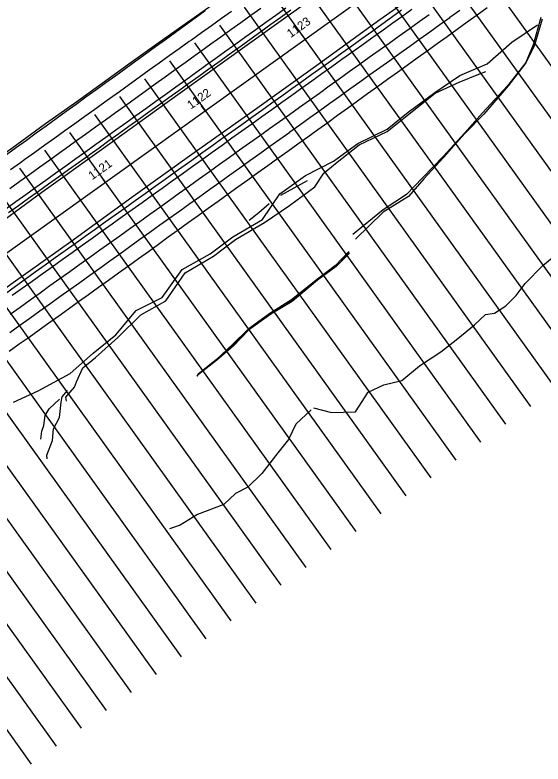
# Model space of a CAD drawing. Extents: x -354 to 8821, y -19535 to 19639.
# Drawn here: x 7812 to 8242, y 1583 to 2193 of the extents above; entities that cross this region are included whole.
import ezdxf

# ---------------------------------------------------------------- set-up
doc = ezdxf.new("R2010")
doc.units = 0
for name, color, linetype in [('PV_X_COP', 7, 'Continuous'), ('PV_X_EOP', 7, 'Continuous'), ('PV_X_Shoulder_Aggregate', 7, 'Continuous'), ('RW_X_CL_50', 7, 'Continuous'), ('SC_Scratch1', 7, 'Continuous'), ('SV_X_Edge_of_Slip', 7, 'Continuous'), ('SV_X_Toe_of_Slope', 7, 'Continuous'), ('SV_X_Top_of_Bank', 7, 'Continuous')]:
    doc.layers.add(name, color=color, linetype=linetype)

msp = doc.modelspace()

# ---------------------------------------------------------------- linework, layer by layer
at = {"layer": 'PV_X_COP'}
for points in [[(7807.73, 2051.83), (7815.85, 2057.67), (7823.97, 2063.5), (7832.09, 2069.34), (7840.21, 2075.17), (7848.33, 2081.01), (7853.03, 2084.39), (7861.15, 2090.22), (7869.27, 2096.06), (7877.39, 2101.9), (7885.51, 2107.73), (7893.63, 2113.57), (7901.75, 2119.41), (7909.87, 2125.24), (7917.99, 2131.08), (7926.11, 2136.92), (7934.23, 2142.75), (7942.35, 2148.59), (7950.47, 2154.43), (7958.59, 2160.27), (7963.29, 2163.64), (7963.29, 2163.64), (7971.41, 2169.48), (7979.53, 2175.32), (7987.65, 2181.15), (7995.77, 2186.99), (8003.89, 2192.82), (8012.01, 2198.66)], [(7807.89, 1949.36), (7816.02, 1955.18), (7824.15, 1961.01), (7832.27, 1966.83), (7840.4, 1972.66), (7848.53, 1978.48), (7856.66, 1984.3), (7864.79, 1990.13), (7872.92, 1995.95), (7881.05, 2001.77), (7889.18, 2007.59), (7897.14, 2013.29), (7905.27, 2019.11), (7913.4, 2024.93), (7921.53, 2030.76), (7929.66, 2036.58), (7937.79, 2042.4), (7945.92, 2048.22), (7954.05, 2054.04), (7962.18, 2059.86), (7970.32, 2065.68), (7978.45, 2071.5), (7986.58, 2077.32), (7994.71, 2083.14), (8002.85, 2088.95), (8010.98, 2094.77), (8019.11, 2100.59), (8027.07, 2106.28), (8035.2, 2112.1), (8043.34, 2117.92), (8051.47, 2123.73), (8059.61, 2129.55), (8067.74, 2135.37), (8075.88, 2141.18), (8084.01, 2147), (8092.15, 2152.81), (8100.28, 2158.63), (8108.42, 2164.44), (8116.55, 2170.26), (8124.69, 2176.07), (8132.82, 2181.89), (8140.96, 2187.7), (8149.1, 2193.51)]]:
    msp.add_lwpolyline(points, dxfattribs=at)
at = {"layer": 'PV_X_EOP'}
for points in [[(7804.49, 2035.27), (7812.61, 2041.1), (7820.74, 2046.93), (7828.86, 2052.76), (7836.98, 2058.6), (7845.11, 2064.43), (7853.23, 2070.26), (7861.35, 2076.09), (7869.47, 2081.93), (7877.6, 2087.76), (7885.72, 2093.59), (7885.88, 2093.71), (7894, 2099.54), (7902.12, 2105.38), (7910.24, 2111.21), (7918.36, 2117.05), (7926.48, 2122.89), (7934.6, 2128.72), (7942.72, 2134.56), (7950.84, 2140.39), (7958.96, 2146.23), (7967.08, 2152.07), (7967.24, 2152.18), (7967.24, 2152.18), (7975.36, 2158.02), (7983.48, 2163.86), (7991.6, 2169.7), (7999.72, 2175.53), (8007.84, 2181.37), (8015.97, 2187.2), (8024.09, 2193.04), (8032.21, 2198.87)], [(7807.76, 1934.57), (7815.89, 1940.4), (7824.02, 1946.22), (7832.14, 1952.05), (7840.27, 1957.88), (7848.4, 1963.7), (7856.53, 1969.53), (7864.65, 1975.35), (7872.78, 1981.18), (7880.91, 1987), (7889.04, 1992.83), (7897.16, 1998.66), (7905.29, 2004.48), (7905.45, 2004.6), (7913.58, 2010.42), (7921.71, 2016.25), (7929.84, 2022.07), (7937.96, 2027.9), (7946.09, 2033.72), (7954.22, 2039.55), (7962.35, 2045.37), (7970.48, 2051.2), (7978.61, 2057.02), (7986.73, 2062.84), (7994.86, 2068.67), (8002.99, 2074.49), (8011.12, 2080.32), (8019.25, 2086.14), (8027.38, 2091.97), (8035.51, 2097.79), (8035.67, 2097.9), (8043.79, 2103.73), (8051.92, 2109.55), (8060.05, 2115.38), (8068.18, 2121.2), (8076.31, 2127.02), (8084.44, 2132.85), (8092.57, 2138.67), (8100.7, 2144.5), (8108.83, 2150.32), (8116.96, 2156.14), (8125.09, 2161.97), (8133.22, 2167.79), (8141.35, 2173.61), (8149.48, 2179.44), (8157.61, 2185.26), (8165.74, 2191.08), (8165.89, 2191.2), (8174.02, 2197.02)], [(8134.86, 2197.46), (8126.73, 2191.64), (8118.6, 2185.82), (8110.47, 2180), (8102.34, 2174.18), (8094.21, 2168.35), (8086.08, 2162.53), (8077.95, 2156.71), (8069.82, 2150.89), (8061.69, 2145.06), (8053.56, 2139.24), (8045.43, 2133.42), (8037.3, 2127.6), (8029.17, 2121.77), (8021.03, 2115.94), (8012.9, 2110.12), (8004.78, 2104.3), (7996.65, 2098.47), (7988.52, 2092.65), (7980.39, 2086.82), (7972.26, 2081), (7964.13, 2075.18), (7956, 2069.35), (7947.87, 2063.53), (7939.74, 2057.7), (7931.61, 2051.88), (7923.48, 2046.06), (7915.36, 2040.23), (7907.23, 2034.41), (7899.1, 2028.58), (7890.96, 2022.75), (7882.83, 2016.93), (7874.7, 2011.1), (7866.58, 2005.28), (7858.45, 1999.45), (7850.32, 1993.62), (7842.19, 1987.8), (7834.06, 1981.97), (7825.94, 1976.15), (7817.81, 1970.32), (7809.68, 1964.5)], [(7988, 2196.04), (7979.88, 2190.2), (7971.76, 2184.37), (7963.64, 2178.53), (7955.52, 2172.69), (7953.69, 2171.38), (7953.69, 2171.38), (7945.57, 2165.54), (7937.45, 2159.7), (7929.33, 2153.87), (7921.21, 2148.03), (7913.09, 2142.19), (7904.97, 2136.36), (7896.85, 2130.52), (7888.73, 2124.69), (7884.99, 2122.01), (7876.87, 2116.17), (7868.74, 2110.34), (7860.62, 2104.51), (7852.5, 2098.68), (7844.37, 2092.85), (7836.25, 2087.02), (7828.12, 2081.19), (7820, 2075.36), (7816.26, 2072.67), (7808.13, 2066.85)]]:
    msp.add_lwpolyline(points, dxfattribs=at)
at = {"layer": 'PV_X_Shoulder_Aggregate'}
for points in [[(8427.82, 2473.88), (8377.92, 2438.43), (8325.47, 2400.65), (8273.79, 2363.79), (8221.55, 2326.85), (8180.8, 2297.81), (8128.12, 2260.38), (8082.15, 2226.78), (8028.58, 2188.39), (7978.98, 2152.72), (7933.92, 2120.35), (7882.32, 2083.22), (7833.79, 2048.53), (7785.45, 2013.27), (7732.67, 1975.86), (7693.88, 1947.56), (7645.37, 1913.17), (7595.97, 1878.05), (7566.01, 1856.18)], [(8455.97, 2436.7), (8404.42, 2400.06), (8350.84, 2361.5), (8300.75, 2325.62), (8248.8, 2287.69), (8207.76, 2258.6), (8155.02, 2221.78), (8108.79, 2189.02), (8054.7, 2149.69), (8004.91, 2114.31), (7957.66, 2080.83), (7908.19, 2045.16), (7859.18, 2009.79), (7810.29, 1974.92), (7758.63, 1937.48), (7720.6, 1910.02), (7671.27, 1875.01), (7622.48, 1839.57), (7594.92, 1820.15)], [(7567.11, 1911.52), (7587.72, 1926.23), (7611.09, 1942.98), (7635.25, 1960.24), (7658.76, 1977.17), (7686.58, 1996.61), (7710.89, 2014.6), (7737.3, 2033.21), (7761.39, 2051.3), (7784.44, 2067.14), (7809.27, 2084.75), (7836.64, 2104.72), (7860.22, 2121.36), (7882.91, 2137.69), (7906.5, 2154.55), (7929.27, 2170.9), (7954.98, 2189.24), (7981.71, 2208.24)], [(7804.05, 1966.37), (7812.19, 1972.19), (7820.32, 1978), (7828.46, 1983.82), (7836.6, 1989.63), (7844.73, 1995.45), (7852.87, 2001.26), (7861, 2007.08), (7869.14, 2012.89), (7877.27, 2018.71), (7885.41, 2024.53), (7893.54, 2030.34), (7901.67, 2036.16), (7909.81, 2041.98), (7917.94, 2047.79), (7926.07, 2053.61), (7934.21, 2059.43), (7942.34, 2065.25), (7947.73, 2069.11), (7955.87, 2074.92), (7964, 2080.74), (7972.13, 2086.56), (7980.26, 2092.38), (7988.39, 2098.2), (7996.53, 2104.02), (8004.66, 2109.84), (8012.79, 2115.67), (8020.92, 2121.49), (8029.05, 2127.31), (8037.18, 2133.13), (8045.31, 2138.95), (8053.44, 2144.78), (8061.57, 2150.6), (8069.7, 2156.42), (8077.83, 2162.24), (8085.96, 2168.07), (8094.09, 2173.89), (8102.22, 2179.72), (8110.35, 2185.54), (8118.47, 2191.37), (8126.6, 2197.19)], [(7966.72, 2196.4), (7958.63, 2190.53), (7950.63, 2184.72), (7942.54, 2178.85), (7934.45, 2172.98), (7926.35, 2167.11), (7918.25, 2161.24), (7910.16, 2155.37), (7902.06, 2149.5), (7893.96, 2143.63), (7885.87, 2137.76), (7877.77, 2131.9), (7869.67, 2126.03), (7861.66, 2120.24), (7853.56, 2114.37), (7845.46, 2108.51), (7837.36, 2102.65), (7829.26, 2096.79), (7821.15, 2090.93), (7813.05, 2085.07), (7804.94, 2079.21)], [(8036.48, 2196.91), (8028.36, 2191.08), (8020.24, 2185.24), (8012.12, 2179.41), (8004, 2173.57), (7995.88, 2167.73), (7987.76, 2161.9), (7979.64, 2156.06), (7971.52, 2150.22), (7969.63, 2148.86), (7969.63, 2148.86), (7961.51, 2143.03), (7953.39, 2137.19), (7945.27, 2131.35), (7937.15, 2125.52), (7929.03, 2119.68), (7920.91, 2113.85), (7912.79, 2108.01), (7904.66, 2102.18), (7896.54, 2096.35), (7888.42, 2090.51), (7880.3, 2084.68), (7872.17, 2078.85), (7871.7, 2078.51), (7863.57, 2072.68), (7855.45, 2066.85), (7847.32, 2061.02), (7839.2, 2055.19), (7831.07, 2049.36), (7822.95, 2043.53), (7814.82, 2037.7), (7806.7, 2031.87)], [(8196.09, 2198.81), (8187.98, 2192.96), (8179.86, 2187.12), (8171.75, 2181.27), (8163.64, 2175.42), (8155.52, 2169.58), (8147.41, 2163.73), (8139.3, 2157.89), (8131.18, 2152.04), (8123.21, 2146.29), (8115.09, 2140.45), (8106.98, 2134.6), (8098.87, 2128.76), (8090.75, 2122.92), (8082.64, 2117.07), (8074.52, 2111.23), (8066.41, 2105.38), (8058.29, 2099.54), (8050.18, 2093.7), (8042.06, 2087.85), (8033.95, 2082.01), (8025.83, 2076.17), (8017.72, 2070.32), (8009.6, 2064.48), (8001.49, 2058.64), (7993.37, 2052.8), (7985.39, 2047.05), (7977.28, 2041.21), (7969.16, 2035.37), (7961.04, 2029.53), (7952.93, 2023.69), (7944.81, 2017.85), (7936.69, 2012.01), (7928.58, 2006.17), (7920.46, 2000.33), (7912.34, 1994.49), (7904.22, 1988.65), (7896.11, 1982.81), (7887.99, 1976.97), (7879.87, 1971.13), (7871.75, 1965.29), (7863.64, 1959.45), (7855.52, 1953.61), (7847.54, 1947.87), (7839.42, 1942.04), (7831.5, 1936.36), (7823.37, 1930.55), (7815.44, 1924.9), (7807.29, 1919.1)]]:
    msp.add_lwpolyline(points, dxfattribs=at)
at = {"layer": 'RW_X_CL_50'}
for p, q in [((7397.71, 1707.37), (8616.98, 2581.09)), ((8047.99, 2173.35), (8045.08, 2177.42)), ((7966.7, 2115.11), (7963.79, 2119.17)), ((7885.42, 2056.86), (7882.51, 2060.92))]:
    msp.add_line(p, q, dxfattribs=at)
at = {"layer": 'SC_Scratch1'}
for p, q in [((8140.79, 2301.37), (8373.78, 1976.23)), ((8120.47, 2286.81), (8353.46, 1961.67)), ((8100.15, 2272.24), (8333.14, 1947.11)), ((8079.83, 2257.68), (8312.82, 1932.55)), ((8059.51, 2243.12), (8292.5, 1917.98)), ((8039.19, 2228.56), (8272.18, 1903.42)), ((8018.86, 2214), (8251.86, 1888.86)), ((7998.54, 2199.43), (8231.54, 1874.3)), ((7978.22, 2184.87), (8211.22, 1859.73)), ((7957.9, 2170.31), (8190.89, 1845.17)), ((7937.58, 2155.75), (8170.57, 1830.61)), ((7917.26, 2141.19), (8150.25, 1816.05)), ((7896.94, 2126.62), (8129.93, 1801.49)), ((7876.62, 2112.06), (8109.61, 1786.92)), ((7856.3, 2097.5), (8089.29, 1772.36)), ((7835.97, 2082.94), (8068.97, 1757.8)), ((7815.65, 2068.38), (8048.65, 1743.24)), ((7795.33, 2053.81), (8028.33, 1728.68)), ((7775.01, 2039.25), (8008, 1714.11)), ((7754.69, 2024.69), (7987.68, 1699.55)), ((7734.37, 2010.13), (7967.36, 1684.99)), ((7714.05, 1995.57), (7947.04, 1670.43)), ((7693.73, 1981), (7926.72, 1655.87)), ((7673.41, 1966.44), (7906.4, 1641.3)), ((7653.08, 1951.88), (7886.08, 1626.74)), ((7632.76, 1937.32), (7865.76, 1612.18)), ((7612.44, 1922.75), (7845.44, 1597.62)), ((7592.12, 1908.19), (7825.12, 1583.06))]:
    msp.add_line(p, q, dxfattribs=at)
at = {"layer": 'SV_X_Edge_of_Slip'}
for p, q in [((8028.17, 2046.47), (8050.1, 2058.39)), ((8077.36, 1993.13), (8084.02, 1999.98))]:
    msp.add_line(p, q, dxfattribs=at)
for points in [[(7853.92, 1878.64), (7853.33, 1881.9), (7860.24, 1890.01), (7861.87, 1894.34), (7867.22, 1905.59), (7877.3, 1914.07), (7895.54, 1930.33), (7914.26, 1948.96), (7934.7, 1960.22), (7950.45, 1982.99), (7973.48, 1996.6), (7991.27, 2010.27), (8014.91, 2024), (8035.34, 2037.93), (8055.83, 2053.19), (8063.31, 2064.35), (8072.89, 2072.12), (8092.13, 2087.33), (8114.77, 2098.24), (8132.54, 2112.36), (8153.76, 2129.34), (8173.49, 2138.25), (8189.39, 2144.87), (8195.19, 2147.17)], [(8054.88, 1873.04), (8069.61, 1869.32), (8089.12, 1869.92), (8099.48, 1885.88), (8111.97, 1891.88), (8126.81, 1895.53), (8141.26, 1907.27), (8158.36, 1918.78), (8172.35, 1929.65), (8185.82, 1940.62), (8194.87, 1949.12), (8202.21, 1950.26), (8211.45, 1956.29), (8219.75, 1964.62), (8227.26, 1974.29), (8241.45, 1988.96), (8255.42, 2000.41), (8256.25, 2017.66), (8251.64, 2033.1), (8257.06, 2038.08), (8265.09, 2041.93), (8273.75, 2054.01), (8288.57, 2064.01), (8291.7, 2069.53)], [(8002.46, 2026.09), (8010.38, 2032.1), (8018.88, 2039.46)], [(7964.04, 1902.61), (7976.3, 1912.28), (7989.7, 1924.45), (8002.22, 1936.96), (8020.05, 1949.71), (8033.16, 1957.68), (8057.48, 1977.12)], [(7838.05, 1831.55), (7837.78, 1834.7), (7842.38, 1846.64), (7843.15, 1855.93), (7848.22, 1865.4), (7849.55, 1877.65), (7850.2, 1882.09), (7854.65, 1887.32)], [(7832.91, 1847.63), (7833.78, 1854.14), (7835.26, 1858.76), (7836.49, 1866.99), (7839.66, 1872.41), (7848.16, 1880.12)], [(8052.84, 1871.57), (8040.43, 1859.71), (8034.38, 1847.31), (8025.81, 1836.57), (8012.71, 1819.58), (8001.52, 1808.41), (7991.35, 1803.41), (7981.92, 1794.41), (7960.52, 1786.38), (7946.42, 1777.66), (7937.61, 1774.5)]]:
    msp.add_lwpolyline(points, dxfattribs=at)
at = {"layer": 'SV_X_Toe_of_Slope'}
msp.add_lwpolyline([(8240.91, 2189.62), (8234.77, 2168.64), (8227.72, 2154), (8213.24, 2135.34), (8193.41, 2112.28), (8177.88, 2096.38), (8161.03, 2077.43), (8144.71, 2059.59), (8132.14, 2045.16), (8111.53, 2032.55), (8089.14, 2010.65)], dxfattribs=at)
at = {"layer": 'SV_X_Top_of_Bank'}
for points in [[(8239.89, 2191.18), (8233.64, 2168.72), (8227.67, 2154.27), (8212.62, 2135.33), (8192.35, 2113.42), (8177.83, 2096.81), (8160.6, 2078.17), (8143.7, 2060.42), (8130.67, 2046.84), (8111.65, 2034.53), (8086.75, 2014.31)], [(7810.76, 1877.69), (7830.68, 1887.08), (7856.78, 1901.06), (7875.44, 1917.59), (7894.11, 1932.59), (7910.62, 1952.53), (7931.71, 1962.93), (7947.91, 1985.88), (7970.76, 1998.44), (7989.31, 2012.54), (8013.24, 2026.48), (8027.5, 2047.42), (8048.47, 2062.41), (8071.09, 2073.99), (8090.97, 2088.43), (8114.74, 2100.06), (8131.82, 2114), (8153.56, 2129.85), (8173.86, 2143.7), (8196.16, 2153.26), (8216.41, 2170.98), (8237.14, 2185.2)], [(8083.51, 2000.38), (8072.87, 1989.07), (8058, 1977.82), (8037.04, 1961.02), (8019.33, 1949.97), (8001.29, 1936.97), (7989.15, 1925.11), (7975.85, 1912.5), (7961.04, 1900.59), (7959.85, 1899.03)], [(8084.09, 1999.24), (8073.35, 1988.24), (8058.15, 1977.09), (8037.45, 1959.84), (8020.23, 1949.36), (8002.06, 1936.27), (7989.87, 1923.77), (7976.2, 1911.9), (7961.25, 1900.28), (7960.01, 1898.94)]]:
    msp.add_lwpolyline(points, dxfattribs=at)

# ---------------------------------------------------------------- texts
at = {"layer": 'RW_X_CL_50'}
for s, p in [('1123', (8036.32, 2174.22)), ('1122', (7955.1, 2116.02)), ('1121', (7874.76, 2058.45))]:
    msp.add_text(s, height=7, rotation=35.62538, dxfattribs=at).set_placement(p)

doc.saveas('drawing.dxf')
